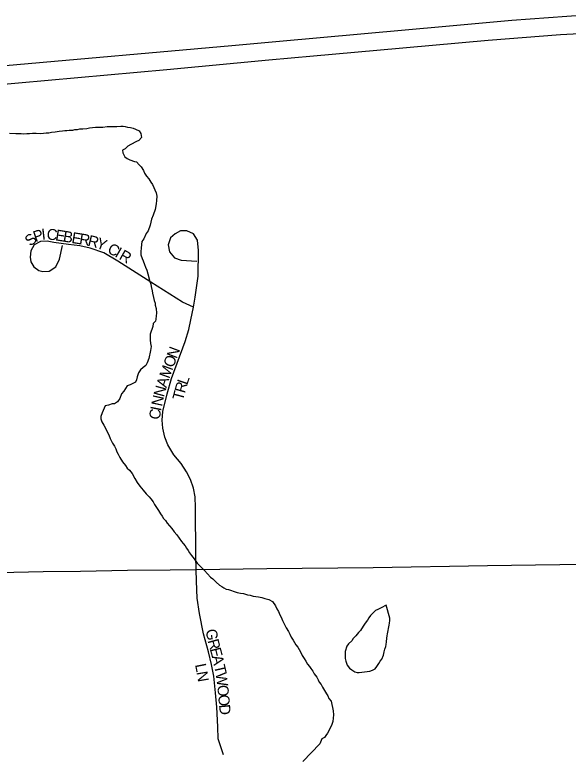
# Model space of a CAD drawing. Extents: x -10.1 to 68, y -9.5 to 29.2.
# Drawn here: x 3.884 to 4.36, y 18.737 to 19.377 of the extents above; entities that cross this region are included whole.
import ezdxf

# ---------------------------------------------------------------- set-up
doc = ezdxf.new("R2010")
doc.units = 0
for name, color, linetype in [('GM_X_Minor_Lake', 7, 'Continuous'), ('GM_X_Minor_River', 7, 'Continuous'), ('GM_X_Township_Road', 7, 'Continuous'), ('GM_X_Township_Subdivision', 7, 'Continuous'), ('GM_X_Township_Subdivision_Text', 7, 'Continuous'), ('GM_X_US_Route', 7, 'Continuous')]:
    doc.layers.add(name, color=color, linetype=linetype)

msp = doc.modelspace()

# ---------------------------------------------------------------- linework, layer by layer
at = {"layer": 'GM_X_Minor_Lake'}
for points in [[(4.2038, 18.86911), (4.19966, 18.86673), (4.19665, 18.86515), (4.19477, 18.86435), (4.19253, 18.8624), (4.19029, 18.86007), (4.18881, 18.85814), (4.18771, 18.85622), (4.18587, 18.85351), (4.18402, 18.85081), (4.18181, 18.84735), (4.17995, 18.8454), (4.17773, 18.84269), (4.1755, 18.84037), (4.1744, 18.83844), (4.17141, 18.83572), (4.16993, 18.83379), (4.16851, 18.82919), (4.16857, 18.82616), (4.16864, 18.82312), (4.16906, 18.82085), (4.17028, 18.81745), (4.17224, 18.81483), (4.17417, 18.81336), (4.17687, 18.81152), (4.17878, 18.81118)], [(4.2038, 18.86911), (4.19966, 18.86673), (4.19665, 18.86515), (4.19477, 18.86435), (4.19253, 18.8624), (4.19029, 18.86007), (4.18881, 18.85814), (4.18771, 18.85622), (4.18587, 18.85351), (4.18402, 18.85081), (4.18181, 18.84735), (4.17995, 18.8454), (4.17773, 18.84269), (4.1755, 18.84037), (4.1744, 18.83844), (4.17141, 18.83572), (4.16993, 18.83379), (4.16851, 18.82919), (4.16857, 18.82616), (4.16864, 18.82312), (4.16906, 18.82085), (4.17028, 18.81745), (4.17224, 18.81483), (4.17417, 18.81336), (4.17687, 18.81152), (4.17878, 18.81118), (4.18068, 18.81122), (4.18296, 18.81127), (4.18979, 18.81218), (4.19206, 18.81299), (4.19431, 18.81418), (4.19579, 18.81611), (4.19764, 18.81881), (4.19874, 18.82073), (4.20022, 18.82266), (4.20167, 18.82611), (4.20199, 18.82878), (4.2027, 18.83108), (4.20342, 18.83337), (4.20375, 18.83528), (4.20409, 18.83757), (4.2044, 18.84061), (4.20474, 18.84252), (4.20508, 18.84443), (4.20541, 18.8471), (4.20575, 18.84901), (4.20645, 18.85168), (4.20679, 18.85359), (4.20712, 18.85588), (4.20708, 18.85778), (4.2038, 18.86911)], [(4.17878, 18.81118), (4.18068, 18.81122), (4.18296, 18.81127), (4.18979, 18.81218), (4.19206, 18.81299), (4.19431, 18.81418), (4.19579, 18.81611), (4.19764, 18.81881), (4.19874, 18.82073), (4.20022, 18.82266), (4.20167, 18.82611), (4.20199, 18.82878), (4.2027, 18.83108), (4.20342, 18.83337), (4.20375, 18.83528), (4.20409, 18.83757), (4.2044, 18.84061), (4.20474, 18.84252), (4.20508, 18.84443), (4.20541, 18.8471), (4.20575, 18.84901), (4.20645, 18.85168), (4.20679, 18.85359), (4.20712, 18.85588), (4.20708, 18.85778), (4.2038, 18.86911)]]:
    msp.add_lwpolyline(points, dxfattribs=at)
at = {"layer": 'GM_X_Minor_River'}
for points in [[(3.87979, 19.27516), (3.88513, 19.2749), (3.88703, 19.27494), (3.88969, 19.275), (3.8916, 19.27466), (3.89464, 19.27473), (3.89692, 19.27478), (3.89957, 19.27522), (3.90262, 19.27528), (3.90681, 19.27499), (3.90909, 19.27504), (3.91136, 19.27547), (3.91364, 19.27552), (3.91592, 19.27595), (3.91895, 19.2764), (3.92236, 19.27685), (3.9254, 19.27729), (3.9273, 19.27734), (3.9292, 19.27738), (3.93109, 19.2778), (3.93413, 19.27786), (3.93603, 19.27829), (3.93831, 19.27833), (3.9402, 19.27876), (3.94286, 19.27881), (3.94628, 19.27927), (3.94855, 19.2797), (3.9512, 19.28014), (3.95387, 19.28019), (3.95615, 19.28024), (3.95805, 19.28028), (3.95995, 19.28033), (3.96374, 19.28079), (3.96678, 19.28085), (3.96983, 19.28092), (3.97211, 19.28097), (3.97553, 19.28104), (3.97743, 19.28108), (3.97934, 19.28075), (3.98125, 19.28041), (3.98392, 19.28009), (3.98622, 19.27938), (3.98813, 19.27866), (3.99121, 19.2772), (3.99278, 19.27496), (3.99323, 19.27155), (3.99101, 19.26884), (3.98912, 19.26804), (3.98424, 19.26527), (3.9816, 19.26408), (3.97936, 19.26175), (3.97711, 19.26056), (3.97716, 19.25828), (3.97913, 19.2549), (3.98106, 19.25342)], [(3.98106, 19.25342), (3.98337, 19.25233), (3.9872, 19.25089), (3.98911, 19.25056), (3.99145, 19.24795), (3.99301, 19.24608), (3.99498, 19.24308), (3.99579, 19.24082), (3.99774, 19.2382), (3.99969, 19.23597), (4.00128, 19.23296), (4.00284, 19.23109), (4.00604, 19.22394), (4.00648, 19.22091), (4.00618, 19.2171), (4.00586, 19.21444), (4.0052, 19.20948), (4.00341, 19.2045), (4.00196, 19.20105), (4.00092, 19.19609), (3.99913, 19.19111), (3.99728, 19.18879), (3.99547, 19.18419), (3.99362, 19.18187), (3.99297, 19.17653), (3.99267, 19.17311), (3.99272, 19.17045), (3.99393, 19.16744), (3.99474, 19.16517), (3.99594, 19.16216), (3.99675, 19.15989), (3.99795, 19.15726), (3.99877, 19.15424), (4.00044, 19.14743), (4.00125, 19.14517), (4.00167, 19.14328), (4.00251, 19.1395), (4.00293, 19.13761), (4.00377, 19.13383), (4.00421, 19.13117), (4.00502, 19.12891), (4.00506, 19.12701), (4.00588, 19.12437), (4.00635, 19.1202), (4.00601, 19.11791), (4.00569, 19.11524), (4.00535, 19.11334), (4.00349, 19.1114), (4.00317, 19.10873), (4.00064, 19.10221), (4.00071, 19.09917), (4.00075, 19.09727), (4.00119, 19.09424), (4.00163, 19.09159), (4.00094, 19.08816), (3.99956, 19.08129), (3.99813, 19.07746), (3.99703, 19.07515), (3.99479, 19.07358), (3.99254, 19.07163), (3.9907, 19.06894), (3.98963, 19.06549), (3.98893, 19.06282), (3.98821, 19.0609), (3.98369, 19.05852), (3.98105, 19.05771), (3.9781, 19.05308), (3.97625, 19.05076), (3.97481, 19.04693), (3.97259, 19.04384), (3.96996, 19.04226), (3.96806, 19.04222), (3.96505, 19.04101), (3.96201, 19.04057), (3.95948, 19.03443), (3.9584, 19.03137), (3.95845, 19.02947), (3.95926, 19.02683), (3.96085, 19.02382), (3.96521, 19.01556), (3.96642, 19.01254), (3.9684, 19.0084), (3.96998, 19.00578), (3.97117, 19.00353), (3.97199, 19.00088), (3.97317, 18.99901), (3.97475, 18.996), (3.97712, 18.99225), (3.97946, 18.98926), (3.98103, 18.98702), (3.98297, 18.98516), (3.98532, 18.98217), (3.98769, 18.97804), (3.98967, 18.97466), (3.99202, 18.97129), (3.99475, 18.96793), (3.99748, 18.96495), (3.99982, 18.96234), (4.00138, 18.96048), (4.00334, 18.95786), (4.00452, 18.95561)], [(4.00452, 18.95561), (4.0061, 18.95298), (4.00806, 18.95036), (4.00964, 18.94774), (4.01121, 18.94549), (4.01239, 18.94361), (4.01395, 18.94175), (4.01552, 18.9395), (4.01747, 18.93726), (4.01942, 18.93503), (4.02138, 18.93203), (4.02372, 18.92942), (4.02568, 18.9268), (4.02765, 18.9238), (4.02921, 18.92194), (4.03077, 18.92007), (4.03195, 18.9182), (4.03352, 18.91595), (4.0347, 18.91408), (4.03627, 18.91183), (4.03862, 18.90884), (4.04136, 18.9051), (4.04525, 18.90101), (4.04758, 18.89878), (4.05264, 18.89318), (4.05458, 18.89171), (4.05769, 18.88873), (4.0604, 18.88613), (4.06233, 18.88504), (4.06425, 18.88394), (4.06618, 18.88284), (4.06809, 18.8825), (4.07, 18.88178), (4.07307, 18.88071), (4.07575, 18.88001), (4.07843, 18.8793), (4.0811, 18.87898), (4.08454, 18.87792), (4.08683, 18.87758), (4.08951, 18.87688), (4.0918, 18.87655), (4.09409, 18.87622), (4.09677, 18.87552), (4.09944, 18.87482), (4.10289, 18.87375), (4.10596, 18.8723), (4.10871, 18.86856), (4.1099, 18.86593), (4.11109, 18.86367), (4.1123, 18.86066), (4.11348, 18.85878), (4.11469, 18.85577), (4.11587, 18.85351), (4.11706, 18.85126), (4.11787, 18.84938), (4.11983, 18.84638), (4.12102, 18.84413), (4.12222, 18.84149), (4.1238, 18.83886), (4.12498, 18.83699), (4.12617, 18.83474), (4.12773, 18.83287), (4.1301, 18.82874), (4.13168, 18.82573), (4.13326, 18.82311), (4.13483, 18.82086), (4.13603, 18.81823), (4.13797, 18.81637), (4.13915, 18.8145), (4.14072, 18.81225), (4.14191, 18.81), (4.14425, 18.80701), (4.14544, 18.80475), (4.14624, 18.80287), (4.14781, 18.80062), (4.149, 18.79837), (4.15255, 18.79275), (4.15373, 18.79087), (4.15454, 18.78861), (4.15649, 18.78637), (4.15819, 18.77805), (4.15864, 18.77464), (4.158, 18.76892), (4.15693, 18.76548), (4.15547, 18.76279), (4.15437, 18.76086), (4.15327, 18.75894), (4.15179, 18.75701), (4.15069, 18.75508), (4.14843, 18.75389), (4.14662, 18.74967), (4.13224, 18.73456)]]:
    msp.add_lwpolyline(points, dxfattribs=at)
at = {"layer": 'GM_X_Township_Road'}
msp.add_lwpolyline([(3.45561, 18.89088), (3.49094, 18.89131), (3.52628, 18.8924), (3.58758, 18.89284), (3.61397, 18.89349), (3.62793, 18.89371), (3.65375, 18.89429), (3.704, 18.89517), (3.74088, 18.89539), (3.77116, 18.89582), (3.80452, 18.89604), (3.81967, 18.89626), (3.84315, 18.89692), (3.87058, 18.89714), (3.90877, 18.89802), (3.94081, 18.89824), (3.98142, 18.89912), (4.01785, 18.89956), (4.04023, 18.89978), (4.1011, 18.90044), (4.19251, 18.90156), (4.29113, 18.90314), (4.39448, 18.90471)], dxfattribs=at)
at = {"layer": 'GM_X_Township_Subdivision'}
for points in [[(4.04023, 18.89978), (4.04001, 18.91141), (4.03979, 18.95311), (4.03936, 18.96211), (4.03804, 18.96957), (4.03562, 18.97725), (4.03211, 18.98361), (4.0275, 18.99086), (4.02114, 18.99832), (4.01609, 19.0071), (4.01346, 19.01368), (4.0117, 19.02136), (4.01104, 19.02817), (4.0117, 19.03563), (4.01543, 19.05099), (4.01916, 19.06416), (4.0308, 19.09576), (4.03409, 19.1063), (4.03584, 19.11442), (4.03804, 19.12539), (4.03958, 19.13417), (4.04199, 19.15217), (4.04243, 19.17411), (4.04155, 19.18311), (4.03804, 19.1886), (4.03233, 19.19101), (4.02685, 19.19101), (4.02224, 19.1886), (4.01829, 19.18509), (4.01631, 19.17916), (4.01741, 19.17302), (4.0218, 19.16797), (4.0275, 19.16599), (4.04089, 19.16512)], [(4.03804, 19.12539), (4.0286, 19.12978), (4.00139, 19.1469), (3.97308, 19.1649), (3.961, 19.17214), (3.94915, 19.17631), (3.94016, 19.17828), (3.9305, 19.17938), (3.91799, 19.18114), (3.91206, 19.18223), (3.90636, 19.1818), (3.90109, 19.17894), (3.89824, 19.17389), (3.89758, 19.16841), (3.89824, 19.16446), (3.90065, 19.16007), (3.90504, 19.157), (3.90855, 19.15612), (3.91382, 19.15634), (3.91974, 19.16007), (3.92282, 19.16665), (3.92523, 19.1785)], [(4.06394, 18.74022), (4.05933, 18.75405), (4.05889, 18.76436), (4.05823, 18.78126), (4.05691, 18.79355), (4.0556, 18.80804), (4.05362, 18.81791), (4.05099, 18.82889), (4.0466, 18.84425), (4.04331, 18.86181), (4.04133, 18.87498), (4.04067, 18.88968), (4.04023, 18.89978)]]:
    msp.add_lwpolyline(points, dxfattribs=at)
at = {"layer": 'GM_X_US_Route'}
for points in [[(3.29415, 19.27871), (3.31772, 19.28242), (3.3578, 19.28735), (3.42382, 19.29421), (3.50034, 19.30042), (3.62162, 19.31105), (3.63002, 19.31178), (3.7014, 19.318), (3.78093, 19.32507), (3.84652, 19.33064), (3.87631, 19.33343), (4.07094, 19.35058), (4.1121, 19.35444), (4.25507, 19.3673), (4.31187, 19.37244), (4.37511, 19.37694)], [(3.29667, 19.26288), (3.33336, 19.26827), (3.40217, 19.27663), (3.4221, 19.27834), (3.4654, 19.28177), (3.56615, 19.29056), (3.62192, 19.29526), (3.72948, 19.30449), (3.8015, 19.31092), (3.86174, 19.31628), (4.01521, 19.33), (4.10288, 19.33815), (4.14125, 19.34158), (4.19591, 19.34651), (4.29172, 19.35508), (4.35389, 19.36001), (4.39161, 19.36215)]]:
    msp.add_lwpolyline(points, dxfattribs=at)

# ---------------------------------------------------------------- texts
at = {"layer": 'GM_X_Township_Subdivision_Text'}
for s, rotation, p in [('I', 6.70218, (3.90782, 19.18331)), ('C', 353.60082, (3.91139, 19.1838)), ('S', 41.19106, (3.89787, 19.17734)), ('P', 19.17788, (3.90206, 19.18124)), ('E', 351.02737, (3.91874, 19.18298)), ('B', 350.7812, (3.92531, 19.18194)), ('E', 350.78002, (3.93271, 19.18074)), ('R', 350.78335, (3.93929, 19.17967)), ('R', 345.74586, (3.94648, 19.17851)), ('Y', 339.38769, (3.95349, 19.17675)), ('C', 331.24029, (3.96321, 19.17285)), ('I', 330.07079, (3.96973, 19.16927)), ('R', 330.04425, (3.97334, 19.16719)), ('N', 69.4286, (4.02355, 19.08059)), ('O', 69.45673, (4.02062, 19.07279)), ('M', 70.15382, (4.01724, 19.06341)), ('A', 72.43603, (4.01476, 19.05556)), ('R', 74.10797, (4.03061, 19.05089)), ('L', 70.87373, (4.03262, 19.05797)), ('N', 74.85032, (4.01261, 19.04762)), ('T', 75.16186, (4.02891, 19.04449)), ('N', 77.55415, (4.01084, 19.0396)), ('I', 78.78434, (4.01004, 19.03556)), ('C', 82.64606, (4.00911, 19.02829)), ('G', 279.35096, (4.04853, 18.84773)), ('R', 285.12219, (4.05011, 18.83849)), ('E', 284.35426, (4.05206, 18.83128)), ('A', 283.43199, (4.0537, 18.82486)), ('L', 281.21885, (4.03933, 18.81783)), ('T', 282.78368, (4.05563, 18.81678)), ('N', 279.53061, (4.04061, 18.81137)), ('W', 277.40025, (4.05706, 18.81052)), ('O', 275.29735, (4.05845, 18.79986)), ('O', 275.32375, (4.05922, 18.79156)), ('D', 275.32375, (4.05999, 18.78326))]:
    msp.add_text(s, height=0.00947, rotation=rotation, dxfattribs=at).set_placement(p)

doc.saveas('drawing.dxf')
